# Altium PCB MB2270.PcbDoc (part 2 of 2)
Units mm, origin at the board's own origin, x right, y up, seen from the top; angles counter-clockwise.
Board outline 55.25 x 31 mm, 4 copper layers (Top Layer, Layer 1, Layer 2, Bottom Layer), stack 0.598 mm thick; 43 components, 44 nets, 187 pads, 892 vias.
Unrouted connection lines stored in the file: 111.
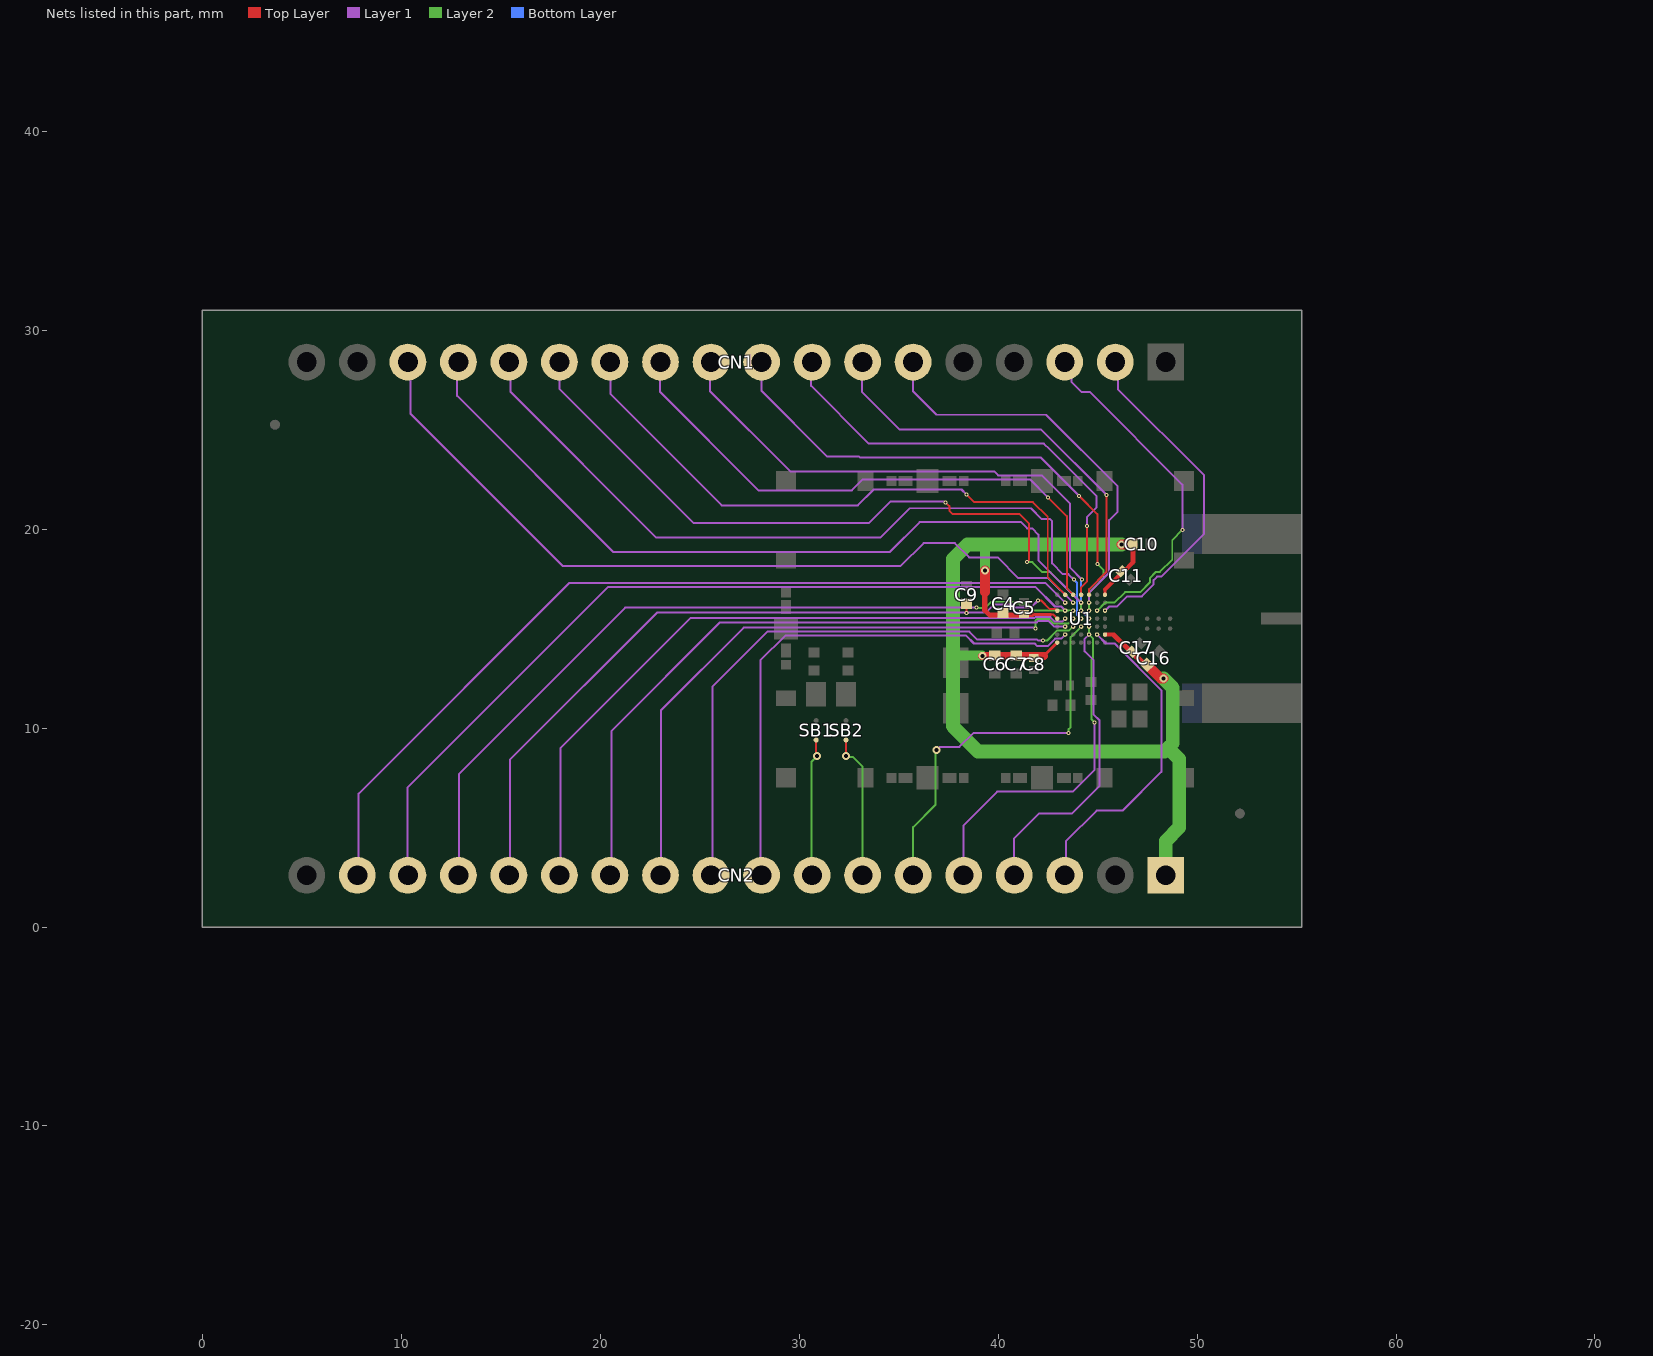
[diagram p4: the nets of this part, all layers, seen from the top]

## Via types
v1: diameter 0.4, hole 0.2, Top Layer to Bottom Layer, tented both sides, 846 vias
v2: diameter 0.2, hole 0.1, Top Layer to Layer 1, tented top, 23 vias
v3: diameter 0.2, hole 0.1, Top Layer to Layer 2, tented top, 10 vias
v4: diameter 0.2, hole 0.1, Layer 1 to Layer 2, tented top, 6 vias
v5: diameter 0.2, hole 0.1, Top Layer to Bottom Layer, tented both sides, 6 vias
v6: diameter 0.3, hole 0.15, Top Layer to Bottom Layer, tented both sides, 1 vias

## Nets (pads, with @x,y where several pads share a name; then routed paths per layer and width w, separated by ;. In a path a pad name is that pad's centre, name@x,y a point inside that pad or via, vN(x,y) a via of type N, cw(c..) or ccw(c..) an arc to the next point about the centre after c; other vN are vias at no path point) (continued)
PA2: CN1.9 U1.E5 | length 26.2
  Top Layer w0.1: v2(44.061,21.675) 44.986,20.75 v3(44.986,18.254)
  Layer 1 w0.1: CN1.9@28.105,28.4 28.105,26.945 31.4,23.65 33.015,23.65 33.065,23.6 42.15,23.6 v2@44.039,21.711
  Layer 2 w0.1: v3(44.569,15.9) 44.569,16.815 45.306,17.553 45.306,17.934 v3(44.986,18.254) v3@45.027,18.254
PA3: CN1.10 U1.E4 | length 27.8
  Layer 1 w0.1: CN1.10@25.505,28.082 25.505,26.945 29.55,22.9 39.8,22.9 40,22.7 42.2,22.7 43.618,21.282 43.618,18.062 v5(44.211,17.469)
  Bottom Layer w0.1: v5@44.215,17.461 44.169,17.415 44.169,15.9 v5(44.569,15.5)
PA4: CN2.5 U1.E3 | length 17.6
  Layer 1 w0.1: CN2.5@38.265,2.6 38.265,5.115 39.95,6.8 43.75,6.8 44.846,7.896 v4(44.846,10.278)
  Layer 2 w0.1: CN2.5@38.265,2.6 CN2.5@38.275,2.61 ; v3(44.569,15.1) 44.569,14.7 44.773,14.496 44.773,13.52 44.691,13.438 44.691,10.433 v4(44.846,10.278)
PA5: CN1.3 U1.F5 | length 17.4
  Layer 1 w0.1: CN1.3@43.345,28.019 43.675,27.689 43.675,27.41 44.185,26.9 44.6,26.9 49.261,22.239 v4(49.261,19.961)
  Layer 2 w0.1: v3(44.969,15.9) 45.369,16.3 45.844,16.3 46.381,16.836 47.14,16.836 47.62,17.316 47.62,17.54 47.932,17.852 48.13,17.852 48.75,18.472 48.75,19.45 v4(49.261,19.961)
PA7: CN1.2 U1.G5 | length 16.8
  Layer 1 w0.1: v2(45.369,15.9) 45.569,16.1 45.954,16.1 46.477,16.623 47.219,16.623 47.815,17.219 47.815,17.438 47.991,17.614 48.199,17.614 50.35,19.764 50.35,22.7 46.013,27.037 46.013,27.825 CN1.2@45.82,28.019
PA8: CN1.7 U1.E7 | length 21.2
  Top Layer w0.1: U1.E7@44.569,16.7 44.569,16.989 45.445,17.865 v2(45.445,21.718)
  Layer 1 w0.1: CN1.7@33.15,28.25 33.15,26.9 35.05,25 42.163,25 v2(45.445,21.718)
PA9: CN1.8 U1.D7 | length 22.6
  Top Layer w0.1: U1.D7@44.173,16.704 44.173,17.077 44.461,17.365 44.461,17.572 44.463,17.574 v2@44.463,20.088
  Layer 1 w0.1: CN1.8@30.6,27.95 30.6,27.2 33.5,24.3 42.3,24.3 42.595,24.005 43.55,23.05 44.95,21.65 44.95,21.1 44.47,20.62 v2(44.47,20.149)
PA10: CN1.6 U1.E6 | length 19.9
  Layer 1 w0.1: CN1.6@35.707,28.082 35.707,26.943 36.9,25.75 42.403,25.75 46,22.153 46,20.875 45.575,20.451 45.575,17.819 44.569,16.813 v2(44.569,16.3)
PA11: CN2.6 U1.D3 | length 19.3
  Layer 1 w0.1: v1@36.872,8.992 36.895,8.969 36.977,8.969 37.059,9.05 38.05,9.05 38.75,9.75 v4(43.523,9.75)
  Layer 2 w0.1: CN2.6@35.725,2.6 35.725,5.025 36.85,6.15 v1@36.85,8.842 ; v4(43.523,9.75) 43.542,9.769 43.542,9.95 43.642,10.05 43.642,14.573 v3(44.169,15.1)
  other v1: 36.9,8.9
PA12: CN1.15 U1.D6 | length 39
  Layer 1 w0.1: CN1.15@12.8,28.1 12.8,26.7 20.65,18.85 34.554,18.85 36.054,20.35 41.15,20.35 41.456,20.044 41.707,20.044 42.024,19.727 42.024,18.446 v2@44.133,16.337 ; v2@44.166,16.3 v2(44.169,16.3)
PA13: CN1.13 U1.D5 | length 34.8
  Top Layer w0.1: v2(37.35,21.35) 37.547,21.153 37.547,20.928 37.724,20.75 41.083,20.75 41.555,20.279 41.555,18.459 v3(41.438,18.343)
  Layer 1 w0.1: CN1.13@17.945,28.4 17.945,27.055 24.7,20.3 33.5,20.3 34.6,21.4 37.273,21.4 37.323,21.35 v2(37.35,21.35)
  Layer 2 w0.1: v3(41.438,18.343) 41.715,18.343 42.215,17.842 42.627,17.842 44.169,16.3 v3(44.169,15.9)
PA14: CN1.11 U1.C7 | length 28.5
  Top Layer w0.1: v2(42.5,21.6) 43.45,20.65 43.45,17.019 U1.C7@43.769,16.7
  Layer 1 w0.1: CN1.11@23,27.85 23,26.9 27.95,21.95 32.65,21.95 33.2,22.5 41.6,22.5 v2(42.5,21.6)
PA15: CN1.16 U1.C6 | length 40.7
  Layer 1 w0.1: CN1.16@10.458,28.25 10.458,25.792 18.1,18.15 35.101,18.15 36.251,19.3 37.818,19.3 38.542,18.576 39.974,18.576 41.008,17.542 42.528,17.542 v2(43.769,16.3)
PB0: CN2.15 U1.C5 | length 39.6
  Layer 1 w0.1: CN2.15@12.9,2.734 12.9,7.7 21.25,16.05 v4(38.9,16.05)
  Layer 2 w0.1: v4(38.9,16.05) 38.906,16.044 39.34,16.044 39.646,16.35 40.817,16.35 40.913,16.254 41.449,16.254 41.803,15.9 v3(43.77,15.9)
PB1: CN2.11 U1.C4 | length 31.4
  Layer 1 w0.1: CN2.11@23.025,2.6 CN2.11@23.1,2.675 ; CN2.11@23.591,3.067 23.391,3.067 23.05,3.408 23.05,10.9 27.2,15.05 41.792,15.05 41.842,14.999 v4(41.869,14.999)
  Layer 2 w0.1: v4(41.869,14.999) 41.869,15.403 41.941,15.475 42.573,15.475 42.797,15.251 43.521,15.251 v3(43.77,15.5) v3@43.77,15.497
PB2: CN1.12 U1.B7 | length 30.8
  Top Layer w0.1: v2@38.45,21.7 38.787,21.363 41.747,21.363 42.492,20.618 42.492,17.578 U1.B7@43.369,16.7
  Layer 1 w0.1: CN1.12@20.5,28.15 20.5,26.8 26.1,21.2 32.95,21.2 33.743,21.993 38.157,21.993 v2(38.4,21.75)
PB3: CN2.17 U1.B6 | length 43.8
  Layer 1 w0.1: CN2.17@7.85,3.191 7.85,6.7 18.45,17.3 42.369,17.3 v2(43.369,16.3)
PB4: CN2.16 U1.B5 | length 41.8
  Layer 1 w0.1: CN2.16@10.3,2.921 10.3,7 20.4,17.1 41.867,17.1 42.857,16.11 43.159,16.11 v2(43.369,15.9)
PB5: CN2.13 U1.B4 | length 34.2
  Layer 1 w0.1: CN2.13@18,3 18,9 24.526,15.526 41.8,15.526 ; 41.821,15.526 41.87,15.574 42.619,15.574 42.843,15.35 43.22,15.35 v2(43.369,15.5)
PB6: CN2.12 U1.B3 | length 32.5
  Layer 1 w0.1: CN2.12@20.485,2.6 20.55,2.665 20.55,9.85 26.017,15.317 41.94,15.317 41.997,15.374 42.537,15.374 42.811,15.099 v2(43.369,15.099)
PB7: CN2.9 U1.B2 | length 26.8
  Layer 1 w0.1: CN2.9@28.05,2.85 28.05,13.4 29.3,14.65 38.384,14.65 38.784,14.25 41.832,14.25 41.946,14.136 42.507,14.136 42.863,14.492 43.161,14.492 v2(43.369,14.7)
PB8: CN1.14 U1.D4 | length 38
  Layer 1 w0.1: CN1.14@15.482,28.082 15.482,26.918 22.822,19.578 34.078,19.578 35.55,21.05 40.75,21.05 41.649,21.05 42.199,20.5 42.61,20.5 42.715,20.395 42.715,18.279 43.251,17.743 43.526,17.743 v5(43.8,17.469)
  Bottom Layer w0.1: v5(43.8,17.469) 43.961,17.307 43.961,15.707 v5(44.169,15.5)
PB9: CN2.10 U1.C3 | length 29.3
  Layer 1 w0.1: CN2.10@25.565,2.6 25.65,2.685 25.65,12.1 28.4,14.85 38.55,14.85 38.95,14.45 41.957,14.45 42.007,14.4 v4(42.245,14.4)
  Layer 2 w0.1: v4@42.19,14.408 42.197,14.4 v4(42.245,14.4) 42.454,14.4 42.954,14.901 43.541,14.901 43.74,15.1 v3(43.77,15.1)
PB12: CN2.7 SB2.1 | length 7.3
  Top Layer w0.1: v1(32.35,8.6) SB2.1@32.35,9.35
  Layer 2 w0.1: v1(32.35,8.6) 32.4,8.55 32.7,8.55 33.185,8.065 CN2.7@33.185,2.6
PB13: CN2.8 SB1.1 | length 7.1
  Top Layer w0.1: SB1.1@30.85,9.35 30.85,8.65 v1(30.9,8.6)
  Layer 2 w0.1: v1(30.9,8.6) 30.62,8.32 30.62,2.88 CN2.8@30.999,2.501
PB14: CN2.4 U1.E2 | length 15.5
  Layer 1 w0.1: CN2.4@40.805,2.6 40.805,4.455 42.05,5.7 43.7,5.7 45.096,7.096 45.096,10.382 44.8,10.678 44.8,13.411 44.35,13.861 44.35,14.481 v2(44.569,14.7) ; CN2.4@40.95,3.1 CN2.4@41.14,3.29
PB15: CN2.3 U1.F2 | length 16.1
  Layer 1 w0.1: CN2.3@43.4,2.9 43.4,4.3 44.95,5.85 46.25,5.85 48.2,7.8 48.2,11.886 ; v2(44.969,14.7) 45.419,14.25 45.85,14.25 48.2,11.9
RSTN: C9.1 CN2.14 U1.A5 | length 37.3
  Top Layer w0.1: v2(38.4,15.776) C9.1@38.4,16.15 ; v2(42.002,16.412) 42.169,16.412 42.598,15.983 42.886,15.983 U1.A5@42.969,15.9
  Layer 1 w0.1: CN2.14@15.405,2.6 CN2.14@15.7,2.895 ; CN2.14@15.45,3.079 15.45,8.4 22.85,15.8 38.305,15.8 38.31,15.795 38.381,15.795 v2(38.4,15.776) 38.419,15.795 38.497,15.795 38.502,15.8 39.385,15.8 39.785,16.2 40.695,16.2 40.845,16.05 41.639,16.05 v2(42.002,16.412)
VDD: C4.2 C5.2 C6.2 C7.2 C8.2 C10.2 C11.2 C16.2 C17.2 CN2.1 U1.A1 U1.A4 U1.G2 U1.G7 | length 59.1
  Top Layer w0.1: 42.659,15.709 42.76,15.709 U1.A4@42.969,15.5
  Top Layer w0.15: U1.G7@45.369,16.7 45.369,16.97 ; 46.769,18.319 46.769,18.34
  Top Layer w0.16: 41.725,15.709 42.659,15.709 ; 42.303,13.633 U1.A1@42.969,14.3
  Top Layer w0.2: U1.G2@45.369,14.7 45.829,14.7 ; 45.369,16.97 C11.2@46.27,17.87
  Top Layer w0.22: C11.2@46.32,17.87 46.769,18.319
  Top Layer w0.25: 39.327,15.918 39.552,15.693 C5.2@41.259,15.693 ; C5.2@41.26,15.709 41.725,15.709 ; 45.812,14.682 46.914,13.613 ; 46.769,18.34 C10.2@46.769,19.224
  Top Layer w0.28: 39.327,15.918 39.327,16.847
  Top Layer w0.296: 46.919,13.618 C16.2@47.505,13.032
  Top Layer w0.4: v1@39.197,13.633 42.303,13.633
  Top Layer w0.5: 39.327,16.847 v1(39.327,17.916) ; v1(46.203,19.219) C10.2@46.754,19.219 ; C16.2@47.482,13.182 48.164,12.5 v1(48.3,12.5)
  Layer 2 w0.5: 38.002,13.644 v1@39.197,13.644 ; v1(39.327,17.916) 39.327,19.011
  Layer 2 w0.7: v1(46.203,19.219) 38.458,19.219 37.732,18.492 37.732,10.09 38.994,8.828 48.367,8.828 48.595,9.055 ; v1(48.3,12.5) 48.777,12.023 48.777,9.238 ; 48.545,9.005 49.1,8.45 49.1,5 48.425,4.325 CN2.1@48.425,2.6 CN2.1@48.645,2.82
  other v1: 39.213,13.635

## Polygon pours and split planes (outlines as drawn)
GND on Bottom Layer "NONET_L-01_P-001" (solid, remove dead copper, pour order 0): 0,31 0,0 55.25,0 55.25,31
GND on Layer 1 "NONET_L-01_P-001" (solid, remove dead copper, pour order 1): 0,31 0,0 55.25,0 55.25,31
GND on Layer 2 "NONET_L-01_P-001" (solid, remove dead copper, pour order 3): 0,31 0,0 55.25,0 55.25,31
GND on Top Layer "NONET_L-01_P-001" (solid, remove dead copper, pour order 2): 0,31 0,0 55.25,0 55.25,31

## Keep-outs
Keep-Out Layer:
  lines w0.1: -0.05,0 ccw(c0,0) 0,-0.05 ; -0.05,0 ccw(c0,0) 0,-0.05 ; -0.05,0 -0.05,31 ; -0.05,31 cw(c0,31) 0,31.05 ; -0.05,31 cw(c0,31) 0,31.05 ; 0,-0.05 55.25,-0.05 ; 0,31.05 55.25,31.05 ; 55.25,-0.05 ccw(c55.25,0) 55.3,0 ; 55.25,-0.05 ccw(c55.25,0) 55.3,0 ; 55.25,31.05 cw(c55.25,31) 55.3,31 ; 55.25,31.05 cw(c55.25,31) 55.3,31 ; 55.3,0 55.3,31

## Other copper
Top Layer:
  pour cut-out: 48.32,15.5 ccw(c48.643,15.5) 48.643,15.177 ccw(c48.643,15.5) 48.966,15.5 ccw(c48.643,15.5) 48.643,15.823 ccw(c48.643,15.5)
  pour cut-out: 47.166,15.5 ccw(c47.489,15.5) 47.489,15.177 ccw(c47.489,15.5) 47.812,15.5 ccw(c47.489,15.5) 47.489,15.823 ccw(c47.489,15.5)
  pour cut-out: 45.369,15.227 45.369,15.772 47.606,15.772 47.606,15.228
  pour cut-out: 44.969,20.771 44.97,19.829 45.52,19.829 45.517,20.771
  pour cut-out: 31.892,10.683 31.892,8.917 32.811,8.917 32.805,10.683
  pour cut-out: 30.392,10.683 30.392,8.917 31.311,8.917 31.305,10.683
  pour cut-out: 49.378,16.103 49.378,14.903 55.278,14.903 55.278,16.103
  pour cut-out: 48.718,15.643 49.178,16.103 49.378,16.103 49.378,14.903 49.172,14.903 48.718,15.357
  region net NetJ1_1: 48.85,15.66 49.378,15.8 49.813,15.8 49.813,15.2 49.378,15.2 48.85,15.34
  pour cut-out: 39,13.45 39.17,13.45 39.17,10.3 39,10.3
  pour cut-out: 39,13.15 39,13.32 43.45,13.32 43.45,13.15
  pour cut-out: 37.234,12.523 37.231,11.761 38.504,11.761 38.504,12.523
  pour cut-out: 40.092,15.189 40.089,14.429 40.666,14.429 40.666,15.189
  pour cut-out: 43.103,15.346 43.103,15.099 42.988,15.199 42.825,15.199 42.825,15.346
  pour cut-out: 43.103,14.86 43.12,14.86 42.825,14.86 42.825,15.001 42.969,14.999 43.103,15.076
  pour cut-out: 44.719,15.771 44.72,14.829 45.27,14.829 45.267,15.771
  pour cut-out: 45.065,16.697 45.189,17.057 45.189,16.7
  pour cut-out: 44.734,16.463 45.198,16.463 45.181,16.48 45.181,16.7 44.746,16.7 44.734,16.688 44.734,16.465
  pour cut-out: 44.674,16.701 44.859,17.074 44.859,16.705
  pour cut-out: 45.27,15.199 45.765,15.199 45.765,15.315 45.268,15.317
  pour cut-out: 45.369,15.205 45.369,14.987 45.27,14.987 45.27,15.204
  pour cut-out: 45.271,14.885 45.767,14.885 45.767,15.001 45.27,15.002
  pour cut-out: 45.619,14.531 45.725,14.423 45.557,14.254 45.449,14.362
  pour cut-out: 45.27,14.799 45.766,14.799 45.766,14.915 45.269,14.917
  pour cut-out: 45.369,14.805 45.369,14.587 45.27,14.587 45.27,14.804
  pour cut-out: 45.261,14.611 45.403,14.468 45.203,14.268 45.06,14.41
  pour cut-out: 45.295,14.234 45.402,14.126 45.21,13.935 45.103,14.042
  pour cut-out: 43.117,16.707 42.959,16.549 43,16.509 43.158,16.667
  pour cut-out: 45.272,14.485 45.767,14.485 45.767,14.601 45.27,14.602
  text ".Layer_Name" at 9.099,-12.163 h3
  text ".GTL" at 50.793,-12.163 h3
Layer 1:
  pour cut-out: 45.35,15.95 48.85,15.95 48.85,15.05 45.35,15.05
  pour cut-out: 48.85,14.6 48.85,16.4 55.25,16.4 55.25,14.6
  pour cut-out: 39,13.15 43.025,13.15 43.025,10.4 39,10.4
  pour cut-out: 44.72,15.771 45.504,15.771 45.504,14.829 44.72,14.829
  pour cut-out: 44.719,15.771 44.72,14.829 45.27,14.829 45.267,15.771
  text ".Layer_Name" at 9.099,-12.163 h3
  text ".G1" at 50.793,-12.163 h3
Layer 2:
  pour cut-out: 39,13.15 43.025,13.15 43.025,10.4 39,10.4
  pour cut-out: 44.72,15.771 45.504,15.771 45.504,14.829 44.72,14.829
  pour cut-out: 44.719,15.771 44.72,14.829 45.27,14.829 45.267,15.771
  text ".G2" at 39.59,-12.195 h3
  text ".Layer_Name" at 80.904,-12.195 h3
Bottom Layer:
  text ".GBL" at 39.59,-12.195 h3
  text ".Layer_Name" at 80.904,-12.195 h3

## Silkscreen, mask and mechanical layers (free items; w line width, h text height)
Top Overlay:
  lines w0.2: 41.5,14.516 41.5,15.15
  text "MB2270" at 11.819,20.569 h3 r270
  text ".Layer_Name" at 9.099,-12.163 h3
  text ".GTO" at 50.793,-12.163 h3
Bottom Overlay:
  text "RX" at 32.827,24.877 h0.8 r270
  text "TX" at 30.277,24.827 h0.8 r270
  text "GND" at 4.827,24.177 h0.8 r270
  text "GND" at 7.277,24.177 h0.8 r270
  text "GND" at 47.927,24.177 h0.8 r270
  text "PA10" at 35.277,23.727 h0.8 r270
  text "SWDIO" at 27.5,22.95 h0.8 r270
  text "SWCLK" at 25.277,22.877 h0.8 r270
  text "GND" at 4.777,4.527 h0.8 r270
  text "RSTN" at 15.227,4.527 h0.8 r270
  text "GND" at 45.677,4.527 h0.8 r270
  text "VDD" at 48.177,4.527 h0.8 r270
  text ".GBO" at 39.59,-12.195 h3
  text ".Layer_Name" at 80.904,-12.195 h3
Top Paste:
  text ".Layer_Name" at 9.099,-12.163 h3
  text ".GTP" at 50.793,-12.163 h3
Bottom Paste:
  text ".GBP" at 39.59,-12.195 h3
  text ".Layer_Name" at 80.904,-12.195 h3
Top Solder:
  text ".Layer_Name" at 9.099,-12.163 h3
  text ".GTS" at 50.793,-12.163 h3
Bottom Solder:
  text ".GBS" at 39.59,-12.195 h3
  text ".Layer_Name" at 80.904,-12.195 h3
Mechanical 1:
  lines w0.1: 55.25,0 55.25,31 ; 55.25,0 55.25,0 ; 55.25,0 0,0 0,31 55.25,31 ; 55.25,31 55.25,31 ; 55.25,31 55.25,31
Bottom Assembly:
  text ".Layer_Name" at 9.099,-12.163 h3
  text ".GM2" at 50.793,-12.163 h3
Mechanical 14:
  the board outline again, w0.254
  text ".Layer_Name" at 9.099,-12.163 h3
  text ".GM14" at 50.793,-12.163 h3
Mechanical 15:
  circle w0.2: c-4.1,-10.71 r0.61
  circle w0.2: c-4.1,-10.71 r1.205
  circle w0.2: c-4.1,41.628 r0.61
  circle w0.2: c-4.1,41.628 r1.205
  circle w0.2: c68.8,15.54 r1.205
  circle w0.2: c68.8,15.54 r0.61
  lines w0.2: -6.2,-10.71 -2,-10.71 ; -6.2,41.628 -2,41.628 ; -4.1,-12.8 -4.1,-8.61 ; -4.1,39.538 -4.1,43.728 ; 66.7,15.54 70.9,15.54 ; 68.8,13.45 68.8,17.64
  lines w0.254: 0,0 55.25,0 55.25,31 0,31 0,0
  text ".GM15" at 39.59,-12.195 h3
  text ".Layer_Name" at 80.904,-12.195 h3
Drill Drawing:
  drawing of 192 lines, arcs and shapes, not listed
  text "Symbol" at 2.598,100.19 h2.16
  text "Count" at 11.059,100.19 h2.16
  text "Hole Size" at 19.838,100.19 h2.16
  text "Plated" at 36.176,100.19 h2.16
  text "Hole Type" at 43.604,100.19 h2.16
  text "Drill Layer Pair" at 54.419,100.19 h2.16
  text "Via/Pad" at 74.918,100.19 h2.16
  text "Pad Shape" at 83.78,100.19 h2.16
  text "Template" at 95.356,100.19 h2.16
  text "1" at 11.059,96.462 h1.8
  text "0.150mm (5.91mil)" at 19.838,96.462 h1.8
  text "PTH" at 36.176,96.462 h1.8
  text "Round" at 43.604,96.462 h1.8
  text "Top Layer - Bottom Layer" at 54.419,96.462 h1.8
  text "Via" at 74.918,96.462 h1.8
  text "Rounded" at 83.78,96.462 h1.8
  text "v30h15m0mx0" at 95.356,96.462 h1.8
  text "36" at 11.059,92.734 h1.8
  text "1.000mm (39.37mil)" at 19.838,92.734 h1.8
  text "PTH" at 36.176,92.734 h1.8
  text "Round" at 43.604,92.734 h1.8
  text "Top Layer - Bottom Layer" at 54.419,92.734 h1.8
  text "Pad" at 74.918,92.734 h1.8
  text "Rounded" at 83.78,92.734 h1.8
  text "(Mixed)" at 95.356,92.734 h1.8
  text "45" at 11.059,89.005 h1.8
  text "0.100mm (3.94mil)" at 19.838,89.005 h1.8
  text "PTH" at 36.176,89.005 h1.8
  text "Round" at 43.604,89.005 h1.8
  text "(Mixed)" at 54.419,89.005 h1.8
  text "Via" at 74.918,89.005 h1.8
  text "Rounded" at 83.78,89.005 h1.8
  text "(Mixed)" at 95.356,89.005 h1.8
  text "846" at 11.059,85.277 h1.8
  text "0.200mm (7.87mil)" at 19.838,85.277 h1.8
  text "PTH" at 36.176,85.277 h1.8
  text "Round" at 43.604,85.277 h1.8
  text "Top Layer - Bottom Layer" at 54.419,85.277 h1.8
  text "Via" at 74.918,85.277 h1.8
  text "Rounded" at 83.78,85.277 h1.8
  text "(Mixed)" at 95.356,85.277 h1.8
  text "928 Total" at 11.059,81.549 h1.8
  text "PCB SPECIFICATIONS :" at 0.953,76.04 h3
  text "A.   MATERIAL :" at 0.953,72.04 h3
  text "FR-4" at 39.453,72.04 h3
  text "X  TG-170" at 55.953,72.04 h3
  text "TG-150" at 74.203,72.04 h3
  text "TG-140" at 90.203,72.04 h3
  text "B.   MATERIAL FAMILY :" at 0.953,69.04 h3
  text "N/A" at 39.453,69.04 h3
  text "C.   SOLDERMASK COLOR :" at 0.953,66.04 h3
  text "X  GREEN" at 39.453,66.04 h3
  text "BLUE" at 55.953,66.04 h3
  text "RED" at 74.203,66.04 h3
  text "BLACK" at 90.203,66.04 h3
  text "D.   SILKSCREEN COLOR :" at 0.953,63.04 h3
  text "X  WHITE" at 39.453,63.04 h3
  text "YELLOW" at 55.953,63.04 h3
  text "BLACK" at 74.203,63.04 h3
  text "E.   SURFACE FINISH :" at 0.953,60.04 h3
  text "X  ENIG" at 39.453,60.04 h3
  text "IMMERSION SILVER" at 55.953,60.04 h3
  text "IMMERSION TIN" at 90.203,60.04 h3
  text "HASL" at 39.453,57.04 h3
  text "HASL (PB-FREE)" at 55.953,57.04 h3
  text "GOLDEN FINGER" at 90.203,57.04 h3
  text "F.   IMPEDANCE CONTROL :" at 0.953,54.04 h3
  text "NO" at 39.453,54.04 h3
  text "X  YES  (SEE IMPEDANCE TABLE FOR DETAIL INFORMATION)" at 55.953,54.04 h3
  text "G.   THROUGH VIA :" at 0.953,51.04 h3
  text "PLUG THE VIAS WHICH ARE COVERED WITH SOLDERMASK ONE OR TWO SIDE." at 39.453,51.04 h3
  text "PLUG MATERIAL :" at 39.453,48.04 h3
  text "X  SOLDERMASK" at 64.953,48.04 h3
  text "NON-CONDUCTIVE EPOXY." at 90.203,48.04 h3
  text "H.   STACK-UP :" at 0.953,45.04 h3
  text "SEE LAYER STACK-UP SEQUENCE FOR OVERALL THICKNESS." at 39.453,45.04 h3
  text "Layer" at 77.952,38.97 h1.8
  text "Name" at 85.488,38.97 h1.8
  text "Material" at 100.063,38.97 h1.8
  text "Thickness" at 115.75,38.97 h1.8
  text "Constant" at 126.508,38.97 h1.8
  text "Top Overlay" at 85.488,35.37 h1.8
  text "Top Solder" at 85.488,31.77 h1.8
  text "Solder Resist" at 100.063,31.77 h1.8
  text "0.020mm" at 115.75,31.77 h1.8
  text "3.5" at 126.508,31.77 h1.8
  text "1" at 77.952,28.17 h1.8
  text "Top Layer" at 85.488,28.17 h1.8
  text "0.035mm" at 115.75,28.17 h1.8
  text "Dielectric 2" at 85.488,24.57 h1.8
  text "TU-768 (1x2113)" at 100.063,24.57 h1.8
  text "0.102mm" at 115.75,24.57 h1.8
  text "4.2" at 126.508,24.57 h1.8
  text "2" at 77.95,20.97 h1.8
  text "Layer 1" at 85.488,20.97 h1.8
  text "0.035mm" at 115.75,20.97 h1.8
  text "Dielectric 1" at 85.488,17.37 h1.8
  text "TU-768 (2x2116)" at 100.063,17.37 h1.8
  text "0.254mm" at 115.75,17.37 h1.8
  text "4.3" at 126.508,17.37 h1.8
  text "3" at 77.952,13.77 h1.8
  text "Layer 2" at 85.488,13.77 h1.8
  text "0.035mm" at 115.75,13.77 h1.8
  text "Dielectric 3" at 85.488,10.17 h1.8
  text "TU-768 (1x2113)" at 100.063,10.17 h1.8
  text "0.102mm" at 115.75,10.17 h1.8
  text "4.2" at 126.508,10.17 h1.8
  text "4" at 77.952,6.57 h1.8
  text "Bottom Layer" at 85.488,6.57 h1.8
  text "0.035mm" at 115.75,6.57 h1.8
  text "Bottom Solder" at 85.488,2.97 h1.8
  text "Solder Resist" at 100.063,2.97 h1.8
  text "0.020mm" at 115.75,2.97 h1.8
  text "3.5" at 126.508,2.97 h1.8
  text "Bottom Overlay" at 85.488,-0.63 h1.8
  text ".Layer_Name" at 9.099,-12.163 h3
  text ".DRL" at 50.793,-12.163 h3
  text "+/- 5%" at 172.19,-20.768 h3
  text "NA" at 158.09,-20.99 h3
  text "0.135" at 127.44,-21.057 h3
  text "57 ohm" at 141.69,-21.057 h3
  text "TOP" at 93.29,-21.207 h3
  text "0.275" at 114.24,-21.207 h3
Mechanical 20:
  circle w0.254: c87.103,-18.884 r1.3
  region: 72.625,-19.977 61.869,-19.977 62.862,-17.484 70.72,-17.484 71.169,-16.725 73.377,-19.273
  region: 86.628,-11.647 71.101,-11.647 70.407,-13.423 69.196,-14.648 67.799,-12.788 67.799,-11.137 68.942,-9.74 70.378,-9.361 86.628,-9.361
  lines w0.254: 62.862,-17.484 71.654,-17.484 68.588,-13.946 cw(c70.392,-12.002) 70.632,-9.361 87.396,-9.361 86.634,-11.647 ; 66.176,-9.114 cw(c68.602,-10.085) 68.839,-7.482 ; 66.215,-9.082 61.869,-19.977 81.191,-19.977 ccw(c81.44,-17.243) 83.989,-18.262 ; 67.955,-13.017 73.377,-19.273 ; 68.209,-13.017 73.514,-19.138 ; 68.209,-12.763 73.514,-18.884 ; 68.307,-11.647 81.3,-11.647 ; 68.336,-12.636 73.641,-18.757 ; 68.463,-12.509 73.768,-18.63 ; 68.59,-12.382 73.895,-18.503 ; 68.717,-12.255 74.022,-18.376 ; 68.772,-10.302 74.077,-16.423 ; 68.84,-7.483 88.29,-7.483 83.99,-18.26 ; 68.844,-12.128 74.094,-18.186 ; 68.844,-11.874 74.149,-17.995 ; 68.844,-11.62 74.149,-17.741 ; 68.844,-10.731 74.149,-16.852 ; 68.971,-11.493 74.276,-17.614 ; 68.971,-11.112 74.276,-17.233 ; 70.343,-17.497 ccw(c70.448,-16.962) 70.745,-16.505 ; 71.429,-11.634 ccw(c71.403,-12.201) 71.073,-12.663 73.438,-15.392 cw(c71.634,-17.336) 72.366,-19.885 ; 77.71,-19.773 80.6,-11.393 ; 77.933,-19.723 80.802,-11.402 ; 78.06,-19.723 80.929,-11.402 ; 78.314,-19.723 81.183,-11.402 ; 78.568,-19.723 81.437,-11.402 ; 78.822,-19.723 81.691,-11.402 ; 79.076,-19.723 81.945,-11.402 ; 79.33,-19.723 82.199,-11.402 ; 79.584,-19.723 82.453,-11.402 ; 79.838,-19.723 82.707,-11.402 ; 80.046,-19.773 82.936,-11.393 ; 82.936,-11.647 86.628,-11.647 ; 85.96,-11.645 86.722,-9.359 ; 86.126,-11.647 86.888,-9.361 ; 86.38,-11.647 87.142,-9.361
  lines w0.3: 0.098,-23.863 90.098,-23.863 90.098,-3.863 0.098,-3.863 ; 0.098,-18.863 60.098,-18.863 ; 0.098,-13.863 60.098,-13.863 ; 0.098,-8.863 60.098,-8.863 ; 0.099,-23.863 0.099,-3.863 ; 40.098,-23.863 40.098,-8.863 ; 60.098,-23.863 60.098,-3.863 ; 77.71,-19.773 80.046,-19.773
  text "Project: '.Board_Name'" at 1.099,-7.079 h3
  text "Layer:" at 1.099,-12.163 h3
  text "Gerber:" at 41.087,-12.163 h3
  text "Variant: '.VariantName'" at 1.099,-17.163 h3
  text "Ref: '.Board_Reference'" at 41.214,-17.163 h3
  text "R" at 86.595,-19.646 h1.52
  text "Date: '.Board_Document_Date'" at 1.099,-22.163 h3
  text "Rev: '.Board_PCB_Revision'" at 41.157,-22.163 h3
Mechanical 21:
  circle w0.254: c3.281,-18.884 r1.3
  region: 3.756,-11.647 19.283,-11.647 19.978,-13.423 21.188,-14.648 22.585,-12.788 22.585,-11.137 21.442,-9.74 20.006,-9.361 3.756,-9.361
  region: 17.759,-19.977 28.515,-19.977 27.522,-17.484 19.664,-17.484 19.216,-16.725 17.007,-19.273
  lines w0.254: 3.242,-9.361 4.004,-11.647 ; 3.496,-9.361 4.258,-11.647 ; 3.662,-9.359 4.424,-11.645 ; 3.75,-11.647 2.988,-9.361 19.752,-9.361 cw(c19.992,-12.002) 21.796,-13.946 18.73,-17.484 27.522,-17.484 ; 3.756,-11.647 7.448,-11.647 ; 6.394,-18.26 2.095,-7.483 21.544,-7.483 ; 6.395,-18.262 ccw(c8.944,-17.243) 9.193,-19.977 28.515,-19.977 24.169,-9.082 ; 7.448,-11.393 10.338,-19.773 ; 7.677,-11.402 10.546,-19.723 ; 7.931,-11.402 10.8,-19.723 ; 8.185,-11.402 11.054,-19.723 ; 8.439,-11.402 11.308,-19.723 ; 8.693,-11.402 11.562,-19.723 ; 8.947,-11.402 11.816,-19.723 ; 9.084,-11.647 22.077,-11.647 ; 9.201,-11.402 12.07,-19.723 ; 9.455,-11.402 12.324,-19.723 ; 9.582,-11.402 12.451,-19.723 ; 9.784,-11.393 12.674,-19.773 ; 16.108,-17.614 21.413,-11.493 ; 16.108,-17.233 21.413,-11.112 ; 16.235,-17.995 21.54,-11.874 ; 16.235,-17.741 21.54,-11.62 ; 16.235,-16.852 21.54,-10.731 ; 16.29,-18.186 21.54,-12.128 ; 16.308,-16.423 21.613,-10.302 ; 16.362,-18.376 21.667,-12.255 ; 16.489,-18.503 21.794,-12.382 ; 16.616,-18.63 21.921,-12.509 ; 16.743,-18.757 22.048,-12.636 ; 16.87,-19.138 22.175,-13.017 ; 16.87,-18.884 22.175,-12.763 ; 17.007,-19.273 22.429,-13.017 ; 18.018,-19.885 cw(c18.75,-17.336) 16.946,-15.392 19.311,-12.663 ccw(c18.981,-12.201) 18.955,-11.634 ; 19.639,-16.505 ccw(c19.937,-16.962) 20.042,-17.497 ; 21.546,-7.482 cw(c21.782,-10.085) 24.208,-9.114
  lines w0.3: 10.338,-19.773 12.674,-19.773 ; 30.098,-23.863 30.098,-3.863 ; 30.098,-18.863 90.098,-18.863 ; 30.098,-13.863 90.098,-13.863 ; 30.098,-8.863 90.098,-8.863 ; 50.098,-23.863 50.098,-8.863 ; 0.098,-23.863 0.098,-3.863 90.098,-3.863 90.098,-23.863 0.098,-23.863
  text "Project: '.Board_Name'" at 88.904,-7.079 h3
  text "Gerber:" at 48.916,-12.163 h3
  text "Layer:" at 88.904,-12.163 h3
  text "Ref: '.Board_Reference'" at 48.916,-17.163 h3
  text "Variant: '.VariantName'" at 88.904,-17.163 h3
  text "R" at 3.789,-19.646 h1.52
  text "Rev: '.Board_PCB_Revision'" at 48.973,-22.163 h3
  text "Date: '.Board_Document_Date'" at 88.904,-22.163 h3

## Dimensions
0,31 to 55.25,31 on Mechanical 16
0,31 to 0,0 on Mechanical 16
